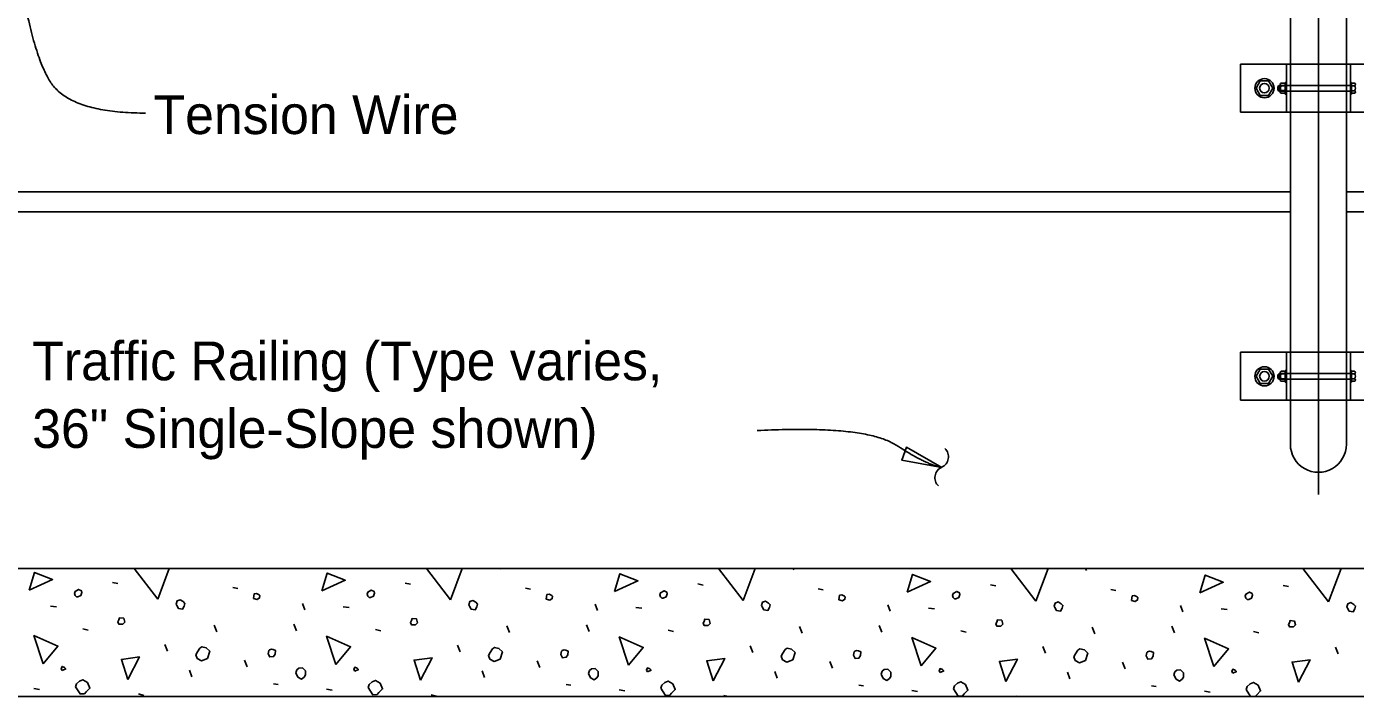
# Model space of a CAD drawing. Extents: x 0 to 41.2, y 0 to 26.
# Drawn here: x 5.48 to 12.4, y 13.8 to 17.29 of the extents above; entities that cross this region are included whole.
import ezdxf

# ---------------------------------------------------------------- set-up
doc = ezdxf.new("R2010")
doc.units = 0
for name, color, linetype in [('CL_Major', 7, 'Continuous'), ('Dimension', 7, 'Continuous'), ('Miscellaneous', 7, 'Continuous'), ('SteelMisc', 7, 'Continuous'), ('SteelMisc_h', 7, 'Continuous'), ('SupstrConc', 7, 'Continuous'), ('TextStructures', 7, 'Continuous')]:
    doc.layers.add(name, color=color, linetype=linetype)

msp = doc.modelspace()

# ---------------------------------------------------------------- linework, layer by layer
at = {"layer": 'CL_Major'}
msp.add_line((12.2062, 25.2199), (12.2062, 14.8548), dxfattribs=at)
at = {"layer": 'Dimension'}
msp.add_lwpolyline([(10.2447, 14.9952), (10.0611, 15.0997), (10.0369, 15.0334)], close=True, dxfattribs=at)
for centre, start, end in [((10.2205, 15.0503), 294.14658, 45.87379), ((10.2692, 14.9415), 114.14657, 225.87379)]:
    msp.add_arc(centre, 0.0596, start, end, dxfattribs=at)
for points in [[(6.1, 16.8398), (5.7021, 16.8398), (5.4981, 17.1768), (5.4369, 17.6337)], [(9.284, 15.1869), (9.8469, 15.2152), (10.1683, 15.0071), (10.2449, 14.9959)]]:
    msp.add_open_spline(points, degree=2, dxfattribs=at)
at = {"layer": 'Miscellaneous'}
for p, q in [((11.9986, 16.9625), (11.9986, 16.9746)), ((12.0044, 16.9625), (12.0044, 16.9746)), ((11.9986, 15.4625), (11.9986, 15.4746)), ((12.0044, 15.4625), (12.0044, 15.4746)), ((7.9504, 14.4659), (7.9491, 14.4695)), ((9.4742, 14.4624), (9.4716, 14.4695)), ((10.9981, 14.4588), (10.9942, 14.4695)), ((5.9281, 14.3952), (5.9546, 14.3899)), ((7.4519, 14.3917), (7.4784, 14.3864)), ((6.5539, 14.3705), (6.5804, 14.3652)), ((8.0777, 14.3669), (8.1042, 14.3616)), ((8.9757, 14.3881), (9.0023, 14.3828)), ((9.6015, 14.3634), (9.628, 14.3581)), ((10.4996, 14.3846), (10.5261, 14.3793)), ((11.1253, 14.3599), (11.1519, 14.3545)), ((12.0234, 14.3811), (12.0499, 14.3758)), ((5.6046, 14.2732), (5.6364, 14.2697)), ((6.9287, 14.2538), (6.9163, 14.2874)), ((7.1284, 14.2697), (7.1602, 14.2662)), ((8.4525, 14.2502), (8.4401, 14.2838)), ((8.6522, 14.2662), (8.6841, 14.2626)), ((9.9763, 14.2467), (9.9639, 14.2803)), ((10.1761, 14.2626), (10.2079, 14.2591)), ((11.5001, 14.2432), (11.4877, 14.2768)), ((11.6999, 14.2591), (11.7317, 14.2556)), ((5.7725, 14.1548), (5.8008, 14.1477)), ((6.4708, 14.1389), (6.4567, 14.1742)), ((6.8862, 14.1442), (6.8721, 14.1795)), ((7.2964, 14.1513), (7.3246, 14.1442)), ((7.9946, 14.1353), (7.9805, 14.1707)), ((8.4101, 14.1406), (8.3959, 14.176)), ((8.8202, 14.1477), (8.8485, 14.1406)), ((9.5184, 14.1318), (9.5043, 14.1672)), ((9.9339, 14.1371), (9.9197, 14.1725)), ((10.344, 14.1442), (10.3723, 14.1371)), ((11.0423, 14.1283), (11.0281, 14.1636)), ((11.4577, 14.1336), (11.4435, 14.1689)), ((11.8678, 14.1406), (11.8961, 14.1336)), ((6.2145, 14.0381), (6.2003, 14.0735)), ((7.7383, 14.0346), (7.7242, 14.0699)), ((9.2621, 14.031), (9.248, 14.0664)), ((10.7859, 14.0275), (10.7718, 14.0629)), ((12.3097, 14.024), (12.2956, 14.0593)), ((6.6281, 13.9568), (6.614, 13.9922)), ((8.152, 13.9533), (8.1378, 13.9886)), ((9.6758, 13.9497), (9.6616, 13.9851)), ((11.1996, 13.9462), (11.1854, 13.9815)), ((6.34, 13.9055), (6.3276, 13.9391)), ((7.8638, 13.902), (7.8514, 13.9356)), ((9.3876, 13.8985), (9.3753, 13.9321)), ((10.9114, 13.8949), (10.8991, 13.9285)), ((5.518, 13.8437), (5.548, 13.8384)), ((6.766, 13.8684), (6.7908, 13.8649)), ((7.0418, 13.8401), (7.0719, 13.8348)), ((8.2898, 13.8649), (8.3146, 13.8613)), ((9.8137, 13.8613), (9.8384, 13.8578)), ((11.3375, 13.8578), (11.3622, 13.8543)), ((6.0625, 13.8154), (6.0907, 13.8083)), ((7.5863, 13.8118), (7.6146, 13.8048)), ((8.5656, 13.8366), (8.5957, 13.8313)), ((9.1101, 13.8083), (9.1322, 13.8028)), ((10.0894, 13.8331), (10.1195, 13.8278)), ((10.6339, 13.8048), (10.6418, 13.8028)), ((11.6132, 13.8295), (11.6433, 13.8242))]:
    msp.add_line(p, q, dxfattribs=at)
for points in [[(6.1632, 14.3086), (6.041, 14.4695)], [(6.2233, 14.4695), (6.1632, 14.3086)], [(7.687, 14.305), (7.5621, 14.4695)], [(7.7485, 14.4695), (7.687, 14.305)], [(9.2109, 14.3015), (9.0832, 14.4695)], [(9.2736, 14.4695), (9.2109, 14.3015)], [(10.7347, 14.298), (10.6043, 14.4695)], [(10.7988, 14.4695), (10.7347, 14.298)], [(12.2585, 14.2944), (12.1255, 14.4695)], [(12.3239, 14.4695), (12.2585, 14.2944)], [(5.4932, 14.3563), (5.5215, 14.4482), (5.6152, 14.4111), (5.4932, 14.3563)], [(7.0171, 14.3528), (7.0453, 14.4447), (7.139, 14.4076), (7.0171, 14.3528)], [(8.5409, 14.3492), (8.5692, 14.4412), (8.6628, 14.404), (8.5409, 14.3492)], [(10.0647, 14.3457), (10.093, 14.4376), (10.1867, 14.4005), (10.0647, 14.3457)], [(11.5885, 14.3422), (11.6168, 14.4341), (11.7105, 14.397), (11.5885, 14.3422)], [(5.7407, 14.321), (5.7478, 14.321), (5.7619, 14.328), (5.7672, 14.3439), (5.7655, 14.3528), (5.7513, 14.3599), (5.7337, 14.3492), (5.7301, 14.3386), (5.7337, 14.328), (5.7407, 14.321)], [(6.6617, 14.3121), (6.6812, 14.3068), (6.6935, 14.3157), (6.6953, 14.328), (6.6918, 14.3316), (6.6776, 14.3386), (6.6653, 14.3369), (6.6635, 14.3245), (6.6617, 14.3121)], [(7.2645, 14.3174), (7.2716, 14.3174), (7.2858, 14.3245), (7.2911, 14.3404), (7.2893, 14.3492), (7.2751, 14.3563), (7.2575, 14.3457), (7.2539, 14.3351), (7.2575, 14.3245), (7.2645, 14.3174)], [(8.1855, 14.3086), (8.205, 14.3033), (8.2174, 14.3121), (8.2191, 14.3245), (8.2156, 14.328), (8.2015, 14.3351), (8.1891, 14.3333), (8.1873, 14.321), (8.1855, 14.3086)], [(8.7884, 14.3139), (8.7954, 14.3139), (8.8096, 14.321), (8.8149, 14.3369), (8.8131, 14.3457), (8.799, 14.3528), (8.7813, 14.3422), (8.7777, 14.3316), (8.7813, 14.321), (8.7884, 14.3139)], [(9.7094, 14.305), (9.7288, 14.2997), (9.7412, 14.3086), (9.7429, 14.321), (9.7394, 14.3245), (9.7253, 14.3316), (9.7129, 14.3298), (9.7111, 14.3174), (9.7094, 14.305)], [(10.3122, 14.3104), (10.3192, 14.3104), (10.3334, 14.3174), (10.3387, 14.3333), (10.3369, 14.3422), (10.3228, 14.3492), (10.3051, 14.3386), (10.3016, 14.328), (10.3051, 14.3174), (10.3122, 14.3104)], [(11.2332, 14.3015), (11.2526, 14.2962), (11.265, 14.305), (11.2668, 14.3174), (11.2632, 14.321), (11.2491, 14.328), (11.2367, 14.3263), (11.2349, 14.3139), (11.2332, 14.3015)], [(11.836, 14.3068), (11.8431, 14.3068), (11.8572, 14.3139), (11.8625, 14.3298), (11.8607, 14.3386), (11.8466, 14.3457), (11.8289, 14.3351), (11.8254, 14.3245), (11.8289, 14.3139), (11.836, 14.3068)], [(6.2622, 14.2768), (6.2711, 14.2609), (6.2923, 14.2573), (6.3011, 14.2732), (6.3046, 14.2874), (6.2958, 14.2962), (6.2799, 14.305), (6.264, 14.2997), (6.2587, 14.2838), (6.2622, 14.2768)], [(7.786, 14.2732), (7.7949, 14.2573), (7.8161, 14.2538), (7.8249, 14.2697), (7.8285, 14.2838), (7.8196, 14.2927), (7.8037, 14.3015), (7.7878, 14.2962), (7.7825, 14.2803), (7.786, 14.2732)], [(9.3098, 14.2697), (9.3187, 14.2538), (9.3399, 14.2502), (9.3487, 14.2662), (9.3523, 14.2803), (9.3434, 14.2891), (9.3275, 14.298), (9.3116, 14.2927), (9.3063, 14.2768), (9.3098, 14.2697)], [(10.8337, 14.2662), (10.8425, 14.2502), (10.8637, 14.2467), (10.8726, 14.2626), (10.8761, 14.2768), (10.8672, 14.2856), (10.8513, 14.2944), (10.8354, 14.2891), (10.8301, 14.2732), (10.8337, 14.2662)], [(12.3575, 14.2626), (12.3663, 14.2467), (12.3875, 14.2432), (12.3964, 14.2591), (12.3999, 14.2732), (12.3911, 14.2821), (12.3752, 14.2909), (12.3592, 14.2856), (12.3539, 14.2697), (12.3575, 14.2626)], [(5.9599, 14.1795), (5.9811, 14.1795), (5.9917, 14.1901), (5.9864, 14.2096), (5.9635, 14.2114), (5.9599, 14.2008), (5.9546, 14.1919), (5.9599, 14.1795), (5.9564, 14.1831)], [(7.4837, 14.176), (7.505, 14.176), (7.5156, 14.1866), (7.5103, 14.2061), (7.4873, 14.2078), (7.4837, 14.1972), (7.4784, 14.1884), (7.4837, 14.176), (7.4802, 14.1795)], [(9.0076, 14.1725), (9.0288, 14.1725), (9.0394, 14.1831), (9.0341, 14.2025), (9.0111, 14.2043), (9.0076, 14.1937), (9.0023, 14.1848), (9.0076, 14.1725), (9.004, 14.176)], [(10.5314, 14.1689), (10.5526, 14.1689), (10.5632, 14.1795), (10.5579, 14.199), (10.5349, 14.2008), (10.5314, 14.1901), (10.5261, 14.1813), (10.5314, 14.1689), (10.5278, 14.1725)], [(12.0552, 14.1654), (12.0764, 14.1654), (12.087, 14.176), (12.0817, 14.1954), (12.0587, 14.1972), (12.0552, 14.1866), (12.0499, 14.1778), (12.0552, 14.1654), (12.0517, 14.1689)], [(5.5657, 13.9727), (5.518, 14.1194), (5.6435, 14.0646), (5.5657, 13.9727)], [(7.0895, 13.9692), (7.0418, 14.1159), (7.1673, 14.0611), (7.0895, 13.9692)], [(6.3683, 14.001), (6.3913, 13.9886), (6.4213, 14.001), (6.4337, 14.0381), (6.416, 14.0558), (6.393, 14.0611), (6.3824, 14.054), (6.37, 14.0346), (6.3612, 14.0187), (6.3683, 14.001)], [(6.7377, 14.024), (6.7466, 14.0081), (6.766, 14.0098), (6.7749, 14.0222), (6.7766, 14.0417), (6.7643, 14.047), (6.7554, 14.0487), (6.7448, 14.0452), (6.7413, 14.0417), (6.7377, 14.024)], [(7.8921, 13.9975), (7.9151, 13.9851), (7.9451, 13.9975), (7.9575, 14.0346), (7.9398, 14.0523), (7.9168, 14.0576), (7.9062, 14.0505), (7.8939, 14.031), (7.885, 14.0151), (7.8921, 13.9975)], [(8.6133, 13.9656), (8.5656, 14.1124), (8.6911, 14.0576), (8.6133, 13.9656)], [(9.4159, 13.9939), (9.4389, 13.9815), (9.4689, 13.9939), (9.4813, 14.031), (9.4636, 14.0487), (9.4407, 14.054), (9.4301, 14.047), (9.4177, 14.0275), (9.4088, 14.0116), (9.4159, 13.9939)], [(10.1372, 13.9621), (10.0894, 14.1088), (10.2149, 14.054), (10.1372, 13.9621)], [(10.9397, 13.9904), (10.9627, 13.978), (10.9928, 13.9904), (11.0051, 14.0275), (10.9875, 14.0452), (10.9645, 14.0505), (10.9539, 14.0434), (10.9415, 14.024), (10.9327, 14.0081), (10.9397, 13.9904)], [(11.661, 13.9586), (11.6132, 14.1053), (11.7388, 14.0505), (11.661, 13.9586)], [(6.0077, 13.8914), (5.9741, 13.9957), (6.0678, 14.0081), (6.0077, 13.8914)], [(7.5315, 13.8879), (7.4979, 13.9922), (7.5916, 14.0045), (7.5315, 13.8879)], [(8.2616, 14.0204), (8.2704, 14.0045), (8.2898, 14.0063), (8.2987, 14.0187), (8.3005, 14.0381), (8.2881, 14.0434), (8.2792, 14.0452), (8.2686, 14.0417), (8.2651, 14.0381), (8.2616, 14.0204)], [(9.0553, 13.8843), (9.0217, 13.9886), (9.1154, 14.001), (9.0553, 13.8843)], [(9.7854, 14.0169), (9.7942, 14.001), (9.8137, 14.0028), (9.8225, 14.0151), (9.8243, 14.0346), (9.8119, 14.0399), (9.8031, 14.0417), (9.7924, 14.0381), (9.7889, 14.0346), (9.7854, 14.0169)], [(10.5791, 13.8808), (10.5455, 13.9851), (10.6392, 13.9975), (10.5791, 13.8808)], [(11.3092, 14.0134), (11.318, 13.9975), (11.3375, 13.9992), (11.3463, 14.0116), (11.3481, 14.031), (11.3357, 14.0363), (11.3269, 14.0381), (11.3163, 14.0346), (11.3127, 14.031), (11.3092, 14.0134)], [(12.1029, 13.8772), (12.0693, 13.9815), (12.163, 13.9939), (12.1029, 13.8772)], [(5.6647, 13.9374), (5.6842, 13.9462), (5.6771, 13.9533), (5.6647, 13.9586), (5.6594, 13.9462), (5.6647, 13.9374)], [(6.8827, 13.925), (6.8933, 13.9038), (6.911, 13.8932), (6.9251, 13.9038), (6.9322, 13.9144), (6.9322, 13.9356), (6.9163, 13.9515), (6.8968, 13.9497), (6.888, 13.9409), (6.8827, 13.925)], [(7.1885, 13.9338), (7.208, 13.9427), (7.2009, 13.9497), (7.1885, 13.955), (7.1832, 13.9427), (7.1885, 13.9338)], [(8.4065, 13.9214), (8.4171, 13.9002), (8.4348, 13.8896), (8.4489, 13.9002), (8.456, 13.9108), (8.456, 13.9321), (8.4401, 13.948), (8.4207, 13.9462), (8.4118, 13.9374), (8.4065, 13.9214)], [(8.7123, 13.9303), (8.7318, 13.9391), (8.7247, 13.9462), (8.7123, 13.9515), (8.707, 13.9391), (8.7123, 13.9303)], [(9.9303, 13.9179), (9.9409, 13.8967), (9.9586, 13.8861), (9.9728, 13.8967), (9.9798, 13.9073), (9.9798, 13.9285), (9.9639, 13.9444), (9.9445, 13.9427), (9.9356, 13.9338), (9.9303, 13.9179)], [(10.2362, 13.9267), (10.2556, 13.9356), (10.2485, 13.9427), (10.2362, 13.948), (10.2309, 13.9356), (10.2362, 13.9267)], [(11.4541, 13.9144), (11.4648, 13.8932), (11.4824, 13.8826), (11.4966, 13.8932), (11.5036, 13.9038), (11.5036, 13.925), (11.4877, 13.9409), (11.4683, 13.9391), (11.4594, 13.9303), (11.4541, 13.9144)], [(11.76, 13.9232), (11.7794, 13.9321), (11.7723, 13.9391), (11.76, 13.9444), (11.7547, 13.9321), (11.76, 13.9232)], [(5.7354, 13.8525), (5.7584, 13.8154), (5.7814, 13.8171), (5.7902, 13.826), (5.8097, 13.8454), (5.7973, 13.8755), (5.7725, 13.8896), (5.7549, 13.8826), (5.7407, 13.8684), (5.7354, 13.8525)], [(7.2592, 13.849), (7.2822, 13.8118), (7.3052, 13.8136), (7.314, 13.8224), (7.3335, 13.8419), (7.3211, 13.8719), (7.2964, 13.8861), (7.2787, 13.879), (7.2645, 13.8649), (7.2592, 13.849)], [(8.7831, 13.8454), (8.806, 13.8083), (8.829, 13.8101), (8.8379, 13.8189), (8.8573, 13.8384), (8.8449, 13.8684), (8.8202, 13.8826), (8.8025, 13.8755), (8.7884, 13.8613), (8.7831, 13.8454)], [(10.3069, 13.8419), (10.3298, 13.8048), (10.3528, 13.8065), (10.3617, 13.8154), (10.3811, 13.8348), (10.3687, 13.8649), (10.344, 13.879), (10.3263, 13.8719), (10.3122, 13.8578), (10.3069, 13.8419)], [(11.8738, 13.8028), (11.8766, 13.803), (11.8855, 13.8118), (11.9049, 13.8313), (11.8926, 13.8613), (11.8678, 13.8755), (11.8501, 13.8684), (11.836, 13.8543), (11.8307, 13.8384)], [(11.8307, 13.8384), (11.8527, 13.8028)], [(6.5568, 13.8028), (6.5557, 13.803), (6.5541, 13.8028)]]:
    msp.add_lwpolyline(points, dxfattribs=at)
at = {"layer": 'SteelMisc'}
for p, q in [((12.0604, 17.0944), (12.0604, 17.6079)), ((12.3521, 17.0944), (12.3521, 17.6079)), ((11.8002, 17.0944), (12.6122, 17.0944)), ((11.8002, 16.8444), (11.8002, 17.0944)), ((12.0396, 17.0944), (12.0396, 16.8444)), ((12.3729, 17.0944), (12.3729, 16.8444)), ((11.9958, 16.9774), (12.0015, 16.984)), ((11.9958, 16.9597), (11.9958, 16.9774)), ((11.9958, 16.9597), (12.0015, 16.9541)), ((12.0015, 16.984), (12.008, 16.984)), ((12.0015, 16.9541), (12.0015, 16.984)), ((12.0015, 16.9541), (12.008, 16.9541)), ((12.008, 16.9873), (12.008, 16.9516)), ((12.0127, 16.9824), (12.033, 16.9824)), ((12.0127, 16.9565), (12.033, 16.9565)), ((12.0129, 16.9954), (12.033, 16.9954)), ((12.033, 16.9997), (12.033, 16.9391)), ((12.033, 16.9997), (12.0396, 16.9997)), ((12.033, 16.9954), (12.033, 16.9435)), ((12.3792, 16.9997), (12.3731, 16.9997)), ((12.3939, 16.9954), (12.3791, 16.9954)), ((12.394, 16.9824), (12.3791, 16.9824)), ((12.394, 16.9564), (12.3791, 16.9564)), ((12.3792, 16.9997), (12.3792, 16.9391)), ((12.013, 16.9435), (12.033, 16.9435)), ((12.033, 16.9391), (12.0396, 16.9391)), ((12.3792, 16.9391), (12.3731, 16.9391)), ((12.3939, 16.9434), (12.3791, 16.9434)), ((12.6122, 16.8444), (11.8002, 16.8444)), ((12.0604, 16.8444), (12.0604, 15.5944)), ((12.3521, 16.8444), (12.3521, 15.5944)), ((11.8002, 15.5944), (12.6122, 15.5944)), ((11.8002, 15.3444), (11.8002, 15.5944)), ((12.0396, 15.5944), (12.0396, 15.3444)), ((12.3729, 15.5944), (12.3729, 15.3444)), ((12.033, 15.4997), (12.033, 15.4391)), ((12.033, 15.4997), (12.0396, 15.4997)), ((12.3792, 15.4997), (12.3731, 15.4997)), ((12.3792, 15.4997), (12.3792, 15.4391)), ((11.9958, 15.4774), (12.0015, 15.484)), ((11.9958, 15.4597), (11.9958, 15.4774)), ((11.9958, 15.4597), (12.0015, 15.4541)), ((12.0015, 15.484), (12.008, 15.484)), ((12.0015, 15.4541), (12.0015, 15.484)), ((12.0015, 15.4541), (12.008, 15.4541)), ((12.008, 15.4873), (12.008, 15.4516)), ((12.0127, 15.4824), (12.033, 15.4824)), ((12.0127, 15.4565), (12.033, 15.4565)), ((12.0129, 15.4954), (12.033, 15.4954)), ((12.013, 15.4435), (12.033, 15.4435)), ((12.033, 15.4954), (12.033, 15.4435)), ((12.033, 15.4391), (12.0396, 15.4391)), ((12.3792, 15.4391), (12.3731, 15.4391)), ((12.3939, 15.4954), (12.3791, 15.4954)), ((12.394, 15.4824), (12.3791, 15.4824)), ((12.394, 15.4564), (12.3791, 15.4564)), ((12.3939, 15.4434), (12.3791, 15.4434)), ((12.6122, 15.3444), (11.8002, 15.3444)), ((12.0603, 15.3444), (12.0603, 15.1153)), ((12.3519, 15.1153), (12.3519, 15.3444))]:
    msp.add_line(p, q, dxfattribs=at)
for points in [[(11.9036, 17.007), (11.9469, 17.007), (11.9686, 16.9694), (11.9469, 16.9319), (11.9036, 16.9319), (11.8819, 16.9694)], [(11.9036, 15.507), (11.9469, 15.507), (11.9686, 15.4694), (11.9469, 15.4319), (11.9036, 15.4319), (11.8819, 15.4694)]]:
    msp.add_lwpolyline(points, close=True, dxfattribs=at)
for centre, radius in [((11.9252, 16.9694), 0.05), ((11.9252, 16.9694), 0.025), ((11.9252, 15.4694), 0.05), ((11.9252, 15.4694), 0.025)]:
    msp.add_circle(centre, radius, dxfattribs=at)
for centre, radius, start, end in [((12.0145, 16.9889), 0.00674, 104.48908, 254.18889), ((12.0274, 16.9694), 0.0196, 138.62797, 221.37203), ((12.0145, 16.95), 0.00673, 105.7823, 255.54039), ((12.3922, 16.9889), 0.00673, 285.7823, 75.54039), ((12.3922, 16.95), 0.00674, 284.48908, 74.18889), ((12.3793, 16.9694), 0.0196, 318.62797, 41.37203), ((12.0145, 15.4889), 0.00674, 104.48908, 254.18889), ((12.0274, 15.4694), 0.0196, 138.62797, 221.37203), ((12.0145, 15.45), 0.00673, 105.7823, 255.54039), ((12.3922, 15.4889), 0.00673, 285.7823, 75.54039), ((12.3922, 15.45), 0.00674, 284.48908, 74.18889), ((12.3793, 15.4694), 0.0196, 318.62797, 41.37203)]:
    msp.add_arc(centre, radius, start, end, dxfattribs=at)
msp.add_ellipse((12.2062, 15.1153), major_axis=(0, 0.1458), ratio=0.999499, start_param=1.570796, end_param=4.712389, dxfattribs=at)
at = {"layer": 'SteelMisc_h'}
for p, q in [((12.0604, 17.0944), (12.0604, 16.8444)), ((12.3521, 17.0944), (12.3521, 16.8444)), ((12.3729, 16.984), (12.008, 16.984)), ((12.008, 16.9541), (12.3729, 16.9541)), ((12.0604, 15.5944), (12.0604, 15.3444)), ((12.3521, 15.5944), (12.3521, 15.3444)), ((12.3729, 15.484), (12.008, 15.484)), ((12.008, 15.4541), (12.3729, 15.4541))]:
    msp.add_line(p, q, dxfattribs=at)
at = {"layer": 'SupstrConc'}
for p, q in [((2.352, 16.4295), (12.0604, 16.4295)), ((12.3521, 16.4295), (22.0604, 16.4295)), ((2.352, 16.3254), (12.0604, 16.3254)), ((12.3521, 16.3254), (22.0604, 16.3254)), ((0.8193, 14.4695), (23.5931, 14.4695)), ((0.8193, 13.8028), (23.5931, 13.8028))]:
    msp.add_line(p, q, dxfattribs=at)

# ---------------------------------------------------------------- texts
at = {"layer": 'Dimension'}
for s, p in [('Traffic Railing (Type varies,', (5.5094, 15.4486)), ('36" Single-Slope shown)', (5.5094, 15.0966))]:
    msp.add_text(s, height=0.2016, dxfattribs=at).set_placement(p)
at = {"layer": 'TextStructures'}
msp.add_text('Tension Wire', height=0.2016, dxfattribs=at).set_placement((6.1409, 16.7305))

doc.saveas('drawing.dxf')
